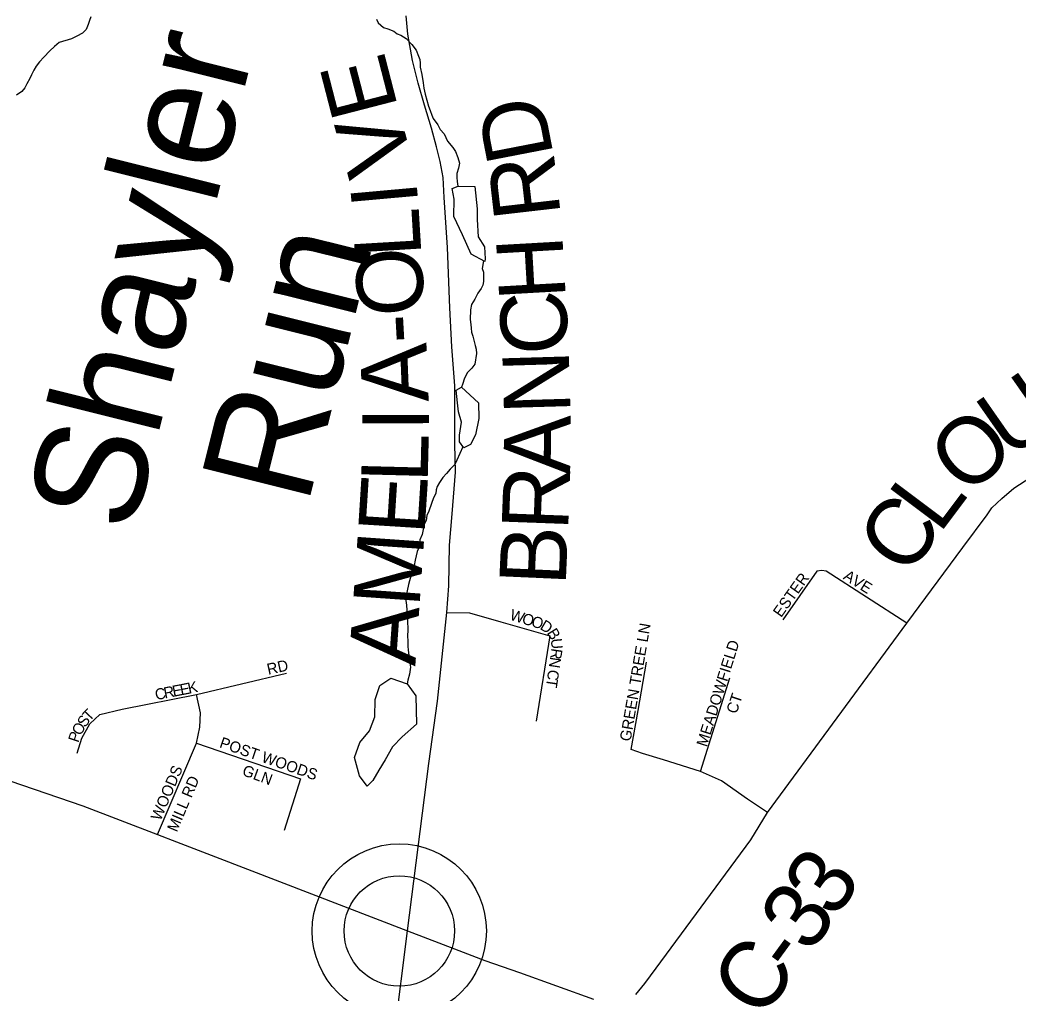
# Model space of a CAD drawing. Extents: x 1310247 to 1664935, y 235267 to 584339.
# Drawn here: x 1477094 to 1481596, y 391172 to 395560 of the extents above; entities that cross this region are included whole.
import ezdxf

# ---------------------------------------------------------------- set-up
doc = ezdxf.new("R2010")
doc.units = 0
for name, color, linetype in [('GM_X_County_Road', 7, 'Continuous'), ('GM_X_County_Road_Text', 7, 'Continuous'), ('GM_X_Minor_Lake', 7, 'Continuous'), ('GM_X_Minor_River', 7, 'Continuous'), ('GM_X_Minor_River_Text', 7, 'Continuous'), ('GM_X_Township_Subdivision', 7, 'Continuous'), ('GM_X_Township_Subdivision_Text', 7, 'Continuous'), ('GM_X_Unincorporated', 7, 'Continuous'), ('GM_X_Unincorporated_Location', 7, 'Continuous')]:
    doc.layers.add(name, color=color, linetype=linetype)

msp = doc.modelspace()

# ---------------------------------------------------------------- linework, layer by layer
at = {"layer": 'GM_X_County_Road'}
for points in [[(1478841.8, 391452.8), (1478841.8, 391452.8), (1478938.8, 392207.1), (1478977.4, 392487.7), (1479020.3, 392888.1), (1479028.3, 393008.6), (1479031.8, 393190.9), (1479044.1, 393333), (1479058.1, 393520.6), (1479056.3, 393648.7), (1479056.3, 393909.9), (1479042.3, 394085.3), (1479033.2, 394261.4), (1479022.8, 394534.2), (1479007.1, 394760), (1479003.2, 394850), (1478988.8, 394921.8), (1478973.2, 394987.1), (1478951, 395071.9), (1478919.1, 395174.9), (1478889.9, 395274.2), (1478865.1, 395376.4), (1478843.2, 395496.2), (1478835.9, 395578)], [(1479871.9, 391165.9), (1479912.2, 391215.7), (1479964.2, 391283.9), (1480390, 391862.6), (1480465.6, 391986.3), (1481093.8, 392839.4), (1481346.3, 393181.8), (1481456.2, 393329.1), (1481477.1, 393360.6), (1481522.2, 393401.5), (1481577.5, 393448.1), (1481699.6, 393529), (1482082.9, 393797.4), (1482804.2, 394294.3), (1483738.8, 393093.4), (1483807.8, 393007.3), (1483879.1, 392945.3), (1483931, 392942), (1483999.6, 392962.2), (1485491.8, 393422.4), (1486077.3, 393602.9), (1486397.1, 393700.6), (1486533.1, 393742.7)], [(1475020.8, 392913.7), (1475170.1, 392846.9), (1475675.5, 392656.7), (1475885.5, 392580.5), (1476146.9, 392458.4), (1476216.2, 392432.6), (1476321.1, 392389.7), (1476449, 392339.4), (1476523.7, 392312.8), (1476613.9, 392278.8), (1476738.2, 392233.7), (1476849.1, 392193.7), (1476937.1, 392166.4), (1477377.1, 392016.2), (1477714.8, 391887.5), (1477800.9, 391853.5), (1477975.4, 391785.5), (1478841.8, 391452.8)], [(1478724.6, 390520.6), (1478841.8, 391452.8)], [(1478841.8, 391452.8), (1479074.2, 391363.8), (1479191.3, 391318.6), (1479347, 391264), (1479681.3, 391144.1)]]:
    msp.add_lwpolyline(points, dxfattribs=at)
at = {"layer": 'GM_X_Minor_Lake'}
for points in [[(1479051.7, 394673.6), (1479053.1, 394751.8), (1479043.9, 394800.1), (1479070.2, 394810.1)], [(1479069, 394810.2), (1479146.4, 394808.3), (1479156.7, 394707.9), (1479155.9, 394659.8), (1479160.6, 394581.4), (1479189.9, 394536.8), (1479193, 394482.6), (1479190.8, 394470.6), (1479129.1, 394503.8), (1479090.4, 394590.7), (1479051.7, 394673.6)], [(1479076.8, 393688.3), (1479085.8, 393746.3), (1479072.6, 393792.7), (1479067.2, 393832.9), (1479062.2, 393891.1), (1479086.4, 393903.4)], [(1479086.4, 393903.4), (1479161.7, 393833.2), (1479164.5, 393763), (1479149.1, 393689), (1479126.3, 393645.3), (1479095.9, 393629.8), (1479076.3, 393658.2), (1479076.8, 393688.3)], [(1478841, 392566.1), (1478879.6, 392512.5), (1478883.4, 392384), (1478818.2, 392327), (1478775.2, 392281.6), (1478742.1, 392224.1), (1478713.1, 392176.4), (1478686.2, 392130.8), (1478659.6, 392105.2), (1478626.3, 392151.9), (1478603.6, 392234.5), (1478626.9, 392302.3), (1478670, 392353.7), (1478695.2, 392417.4), (1478696.5, 392495.6)], [(1478696.5, 392495.6), (1478717.7, 392559.4), (1478766.5, 392592.6), (1478841, 392566.1)]]:
    msp.add_lwpolyline(points, dxfattribs=at)
at = {"layer": 'GM_X_Minor_River'}
for points in [[(1477414, 395573.4), (1477407.8, 395557.4), (1477401.4, 395539.5), (1477393, 395517.5), (1477376.7, 395499.8), (1477350.3, 395486.2), (1477326.1, 395474.6), (1477271.6, 395457.5), (1477249.2, 395439.8), (1477228.8, 395420.1), (1477202.2, 395392.4), (1477181.8, 395370.7), (1477167.4, 395350.9), (1477157.1, 395333), (1477146.7, 395313.1), (1477138.4, 395295.2), (1477125.9, 395271.3), (1477115.6, 395253.4), (1477103.3, 395237.6), (1477078.9, 395220)], [(1478702.6, 395563), (1478710.4, 395546.8), (1478734.1, 395526.3), (1478754.1, 395519.9), (1478780, 395509.4), (1478795.8, 395497.1), (1478811.8, 395490.8), (1478835.6, 395476.3), (1478861.3, 395449.8), (1478880.9, 395423.3), (1478892.5, 395397), (1478898.3, 395380.9), (1478900, 395364.8), (1478899.7, 395346.7), (1478907.2, 395314.5), (1478912.6, 395276.2), (1478916.2, 395252.1), (1478921.8, 395225.9), (1478929.3, 395197.7), (1478936.9, 395171.5), (1478944.6, 395151.2), (1478952.3, 395131), (1478958, 395114.9), (1478979.6, 395086.4), (1478989.3, 395066.2), (1479007.1, 395045.8), (1479022.6, 395013.4), (1479046.2, 394984.9), (1479057.9, 394966.6), (1479069.5, 394940.3), (1479077.1, 394914.1), (1479072.7, 394892.1), (1479064.3, 394868.1), (1479064, 394850.1), (1479065.7, 394832), (1479069, 394810.2)], [(1479184.5, 394474), (1479179.5, 394438.6), (1479185.3, 394422.5)], [(1479185.3, 394422.5), (1479184.9, 394396.4), (1479184.6, 394380.3), (1479182.3, 394364.3), (1479174, 394348.4), (1479159.6, 394328.6), (1479145.1, 394300.8), (1479130.6, 394276.9), (1479126.2, 394252.9), (1479125.5, 394208.8), (1479127.1, 394186.7), (1479128.9, 394170.6), (1479130.6, 394152.5), (1479136.3, 394134.3), (1479147.6, 394092), (1479151.4, 394075.8), (1479153, 394055.8), (1479146.2, 394007.7), (1479131.9, 393989.9), (1479113.5, 393970.1), (1479099, 393944.3), (1479090.5, 393916.3), (1479086.4, 393903.4)], [(1479092.1, 393635.2), (1479064.7, 393575.6), (1479056.3, 393555.7), (1479033.9, 393534), (1479017.5, 393514.2), (1479001.1, 393496.5), (1478986.7, 393474.6), (1478976.4, 393456.8), (1478972.1, 393440.8), (1478969.8, 393424.8), (1478959.4, 393404.9), (1478951, 393378.9), (1478938.4, 393345), (1478930, 393325.1), (1478925.6, 393303.1), (1478917.3, 393285.2), (1478908.5, 393239.2), (1478898.1, 393215.3), (1478897.7, 393195.2), (1478893.4, 393179.3), (1478885.1, 393163.4), (1478876.4, 393123.4), (1478872, 393099.4), (1478865.7, 393081.4), (1478850.8, 393031.5), (1478846.5, 393013.5), (1478840, 392985.5), (1478835.6, 392961.5), (1478835.3, 392941.5), (1478836.9, 392921.4), (1478840.2, 392875.2), (1478841.8, 392855.1), (1478843, 392806.9), (1478842.7, 392784.8), (1478844.2, 392756.7), (1478843.9, 392736.6), (1478845.6, 392718.5), (1478852.6, 392660.2), (1478856.3, 392642.1), (1478851.8, 392610.1), (1478843.3, 392582.1), (1478841, 392566.1)]]:
    msp.add_lwpolyline(points, dxfattribs=at)
at = {"layer": 'GM_X_Township_Subdivision'}
for points in [[(1481093.8, 392839.4), (1480731.1, 393073.7), (1480711.1, 393077.8), (1480689.1, 393074), (1480535.1, 392855.2)], [(1479020.3, 392888.1), (1479121.2, 392885.8), (1479262.6, 392845.5), (1479484.2, 392782.3), (1479422.9, 392398.3)], [(1480465.6, 391986.3), (1480375, 392046.5), (1480258.1, 392128.5), (1480163.5, 392171.3), (1479997.2, 392223.9), (1479901.5, 392252.4), (1479850.4, 392270), (1479883.3, 392446.3), (1479920.8, 392664)], [(1477352, 392253.6), (1477372.7, 392321.7), (1477409.6, 392385.3), (1477454, 392428.2), (1477554.6, 392451.8), (1477890.4, 392518.4), (1478297.1, 392614.5)], [(1480163.5, 392171.3), (1480296.6, 392593)], [(1477714.8, 391887.5), (1477890.4, 392299.5), (1477905.1, 392370.5), (1477908.1, 392435.5), (1477890.4, 392518.4)], [(1477890.4, 392299.5), (1478359.2, 392138.3), (1478285.3, 391904.6)]]:
    msp.add_lwpolyline(points, dxfattribs=at)
at = {"layer": 'GM_X_Unincorporated'}
for radius in [392.8, 249]:
    msp.add_circle((1478805.1, 391451.9), radius, dxfattribs=at)
at = {"layer": 'GM_X_Unincorporated_Location'}
msp.add_line((1478805.1, 391451.9), (1478805.1, 391451.9), dxfattribs=at)

# ---------------------------------------------------------------- texts
at = {"layer": 'GM_X_County_Road_Text'}
for s, rotation, p in [('E', 104.4759, (1478800.7, 395163.6)), ('D', 100.9733, (1479501.9, 394949.1)), ('V', 105.3115, (1478870.1, 394910.1)), ('R', 96.5689, (1479533.9, 394679.5)), ('I', 95.144, (1478891.5, 394730.2)), ('L', 93.3826, (1478905.4, 394496.2)), ('H', 93.2331, (1479556.5, 394304.7)), ('O', 93.2086, (1478920.3, 394231.6)), ('C', 93.0483, (1479569.6, 394057.6)), ('-', 93.1626, (1478927.1, 394108.3)), ('A', 92.2845, (1478937.9, 393839.5)), ('N', 91.6809, (1479577.7, 393785.9)), ('U', 34.9126, (1481555.7, 393574.8)), ('I', 90.2631, (1478938.7, 393704.8)), ('A', 89.5119, (1479575.6, 393509.5)), ('O', 41.3501, (1481364.6, 393405.9)), ('L', 88.5631, (1478932.9, 393470.7)), ('R', 87.903, (1479566.3, 393254.1)), ('E', 86.3957, (1478918.3, 393234.4)), ('L', 53.1181, (1481240.9, 393238.3)), ('C', 53.5344, (1481094.8, 393040.6)), ('B', 87.4662, (1479555.3, 393005.4)), ('M', 86.0173, (1478895.5, 392907.4)), ('A', 86.0153, (1478877.2, 392644)), ('3', 55.6154, (1480768.8, 391500.9)), ('3', 54.1794, (1480655.9, 391344.3)), ('C', 53.7772, (1480436.3, 391044.2)), ('-', 53.8549, (1480582.1, 391243.3))]:
    msp.add_text(s, height=300, rotation=rotation, dxfattribs=at).set_placement(p)
at = {"layer": 'GM_X_Minor_River_Text'}
for s, height, rotation, p in [('Shayler', 499.77, 75.997, (1477604.3, 393236.1)), ('Run', 499.75, 75.9969, (1478391.2, 393364.2))]:
    msp.add_text(s, height=height, rotation=rotation, dxfattribs=at).set_placement(p)
at = {"layer": 'GM_X_Township_Subdivision_Text'}
for s, rotation, p in [('ESTER', 54.4605, (1480527.4, 392862.5)), ('AVE', 327.9938, (1480804, 393041)), ('W', 342.8222, (1479300.1, 392856.6)), ('O', 342.8222, (1479354.7, 392839.7)), ('O', 342.8222, (1479396.8, 392826.7)), ('D', 329.2632, (1479436, 392814.9)), ('GREEN TREE LN', 80.273, (1479848.2, 392304.4)), ('B', 302.1452, (1479469.4, 392796.8)), ('U', 275.0273, (1479488.5, 392769.1)), ('MEADOWFIELD', 72.6124, (1480191.6, 392279)), ('R', 261.4683, (1479492.4, 392728.4)), ('RD', 12.5327, (1478214.2, 392606.6)), ('N', 261.4683, (1479486.5, 392689.3)), ('C', 261.4683, (1479478, 392632.7)), ('E', 11.078, (1477786.2, 392507.5)), ('E', 11.0527, (1477820.7, 392514.2)), ('K', 12.2784, (1477856.4, 392521.2)), ('T', 261.4683, (1479472.2, 392593.5)), ('C', 11.0718, (1477708.4, 392492.3)), ('R', 11.0703, (1477747.3, 392499.9)), ('CT', 71.565, (1480326.1, 392428)), ('S', 55.6505, (1477388.9, 392366.7)), ('T', 47.0295, (1477407.5, 392394.2)), ('O', 59.9434, (1477367.4, 392329.5)), ('P', 71.5737, (1477357.4, 392298.5)), ('POST WOODS', 340.9537, (1477990.5, 392280.7)), ('WOODS', 66.9509, (1477728, 391945.5)), ('GLN', 339.6732, (1478092.8, 392156)), ('MILL RD', 67.0642, (1477801.9, 391894.7))]:
    msp.add_text(s, height=50, rotation=rotation, dxfattribs=at).set_placement(p)

doc.saveas('drawing.dxf')
